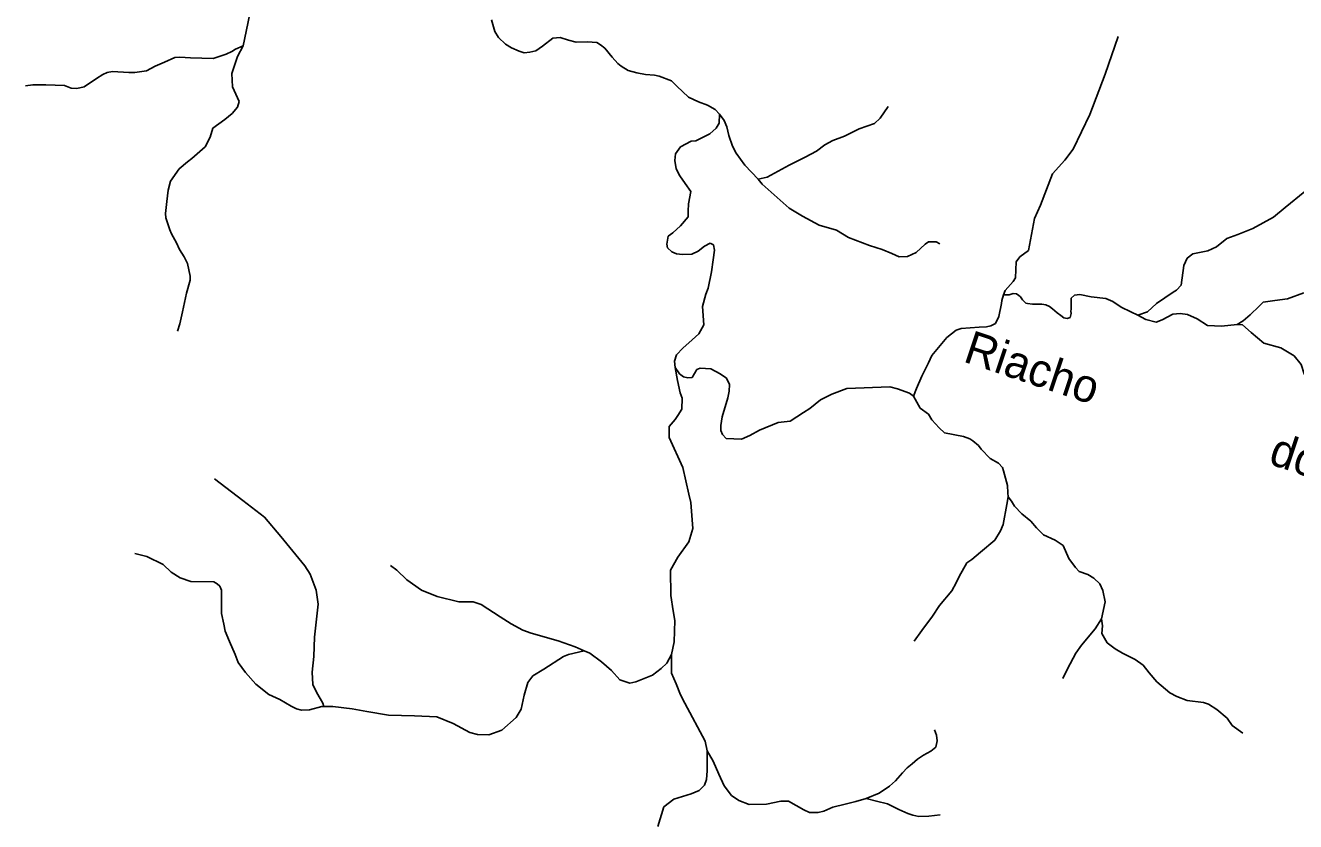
# Model space of a CAD drawing. Extents: x 717.8 to 772.7, y 8672.2 to 8728.
# Drawn here: x 725.59 to 733.27, y 8710.22 to 8715.03 of the extents above; entities that cross this region are included whole.
import ezdxf
from ezdxf.enums import TextEntityAlignment as Align

# ---------------------------------------------------------------- set-up
doc = ezdxf.new("R2010")
doc.units = 0
doc.header["$LTSCALE"] = 0.08
doc.linetypes.add('LONG_DASHED', pattern=[7.5, 6, -1.5])
doc.layers.add('61', color=7, linetype='Continuous')
doc.layers.add('9', color=7, linetype='LONG_DASHED', lineweight=25)

msp = doc.modelspace()

# ---------------------------------------------------------------- linework, layer by layer
at = {"layer": '9'}
for points in [[(726.9071, 8714.9093), (726.935, 8715.0449), (726.9507, 8715.1235), (726.9547, 8715.1579), (727.0132, 8715.2749), (727.0615, 8715.3649), (727.0853, 8715.4872), (727.1001, 8715.5623)], [(729.7892, 8714.4975), (729.762, 8714.5245), (729.7159, 8714.5507), (729.6618, 8714.5718), (729.5998, 8714.5997), (729.5303, 8714.6663), (729.4979, 8714.6976), (729.4239, 8714.7261), (729.3941, 8714.7321), (729.3402, 8714.7378), (729.2884, 8714.7464), (729.2355, 8714.7618), (729.1936, 8714.7871), (729.1729, 8714.8033), (729.1387, 8714.8415), (729.0955, 8714.8961), (729.0678, 8714.9167), (729.0459, 8714.9303), (728.9889, 8714.9335), (728.9206, 8714.9318), (728.8752, 8714.9442), (728.8241, 8714.9599), (728.7794, 8714.9568), (728.7179, 8714.9073), (728.6775, 8714.8794), (728.6416, 8714.8714), (728.6064, 8714.8686), (728.5765, 8714.8774), (728.5294, 8714.8971), (728.494, 8714.9206), (728.4507, 8714.9599), (728.4284, 8714.9966), (728.4091, 8715.0664)], [(732.2004, 8714.9657), (732.122, 8714.7385), (732.0276, 8714.4957), (731.9275, 8714.2859), (731.8778, 8714.2191), (731.8025, 8714.1357), (731.729, 8713.9473), (731.6932, 8713.8671), (731.6582, 8713.673), (731.6051, 8713.6341), (731.5824, 8713.6042), (731.5796, 8713.5085), (731.5639, 8713.485), (731.5156, 8713.4318), (731.5053, 8713.4058)], [(725.5897, 8714.6689), (725.6337, 8714.6746), (725.7132, 8714.674), (725.8271, 8714.6701), (725.8657, 8714.6538), (725.9018, 8714.653), (725.9451, 8714.6614), (726.0195, 8714.7132), (726.0587, 8714.7367), (726.0841, 8714.7499), (726.1175, 8714.7545), (726.2159, 8714.7485), (726.2512, 8714.7485), (726.3221, 8714.7598), (726.3738, 8714.7864), (726.4319, 8714.8113), (726.4937, 8714.8392), (726.5241, 8714.8408), (726.5883, 8714.8385), (726.7257, 8714.8339), (726.804, 8714.8598), (726.8378, 8714.8761), (726.8599, 8714.8897), (726.9071, 8714.9093)], [(726.5089, 8713.1846), (726.5229, 8713.2305), (726.54, 8713.3016), (726.5632, 8713.4155), (726.586, 8713.4937), (726.5871, 8713.5173), (726.5708, 8713.5933), (726.5503, 8713.6343), (726.5226, 8713.6792), (726.5032, 8713.7198), (726.4732, 8713.7741), (726.4637, 8713.7979), (726.4391, 8713.8703), (726.4376, 8713.8961), (726.4461, 8713.9688), (726.4531, 8714.0378), (726.4681, 8714.0924), (726.5199, 8714.1663), (726.5697, 8714.2081), (726.5972, 8714.2284), (726.6768, 8714.2992), (726.7072, 8714.358), (726.7243, 8714.412), (726.7964, 8714.4651), (726.8397, 8714.5001), (726.8735, 8714.5392), (726.8818, 8714.5738), (726.8434, 8714.6615), (726.8393, 8714.7431), (726.8722, 8714.8448), (726.9071, 8714.9093)], [(730.8077, 8714.5436), (730.7611, 8714.4719), (730.7252, 8714.4415), (730.6332, 8714.4083), (730.544, 8714.3646), (730.4747, 8714.3384), (730.4264, 8714.3121), (730.3757, 8714.2725), (730.3068, 8714.2377), (730.2094, 8714.1893), (730.0764, 8714.1169), (730.0219, 8714.1041)], [(729.7892, 8714.4975), (729.7858, 8714.4426), (729.7672, 8714.4119), (729.7304, 8714.3778), (729.6441, 8714.3349), (729.6163, 8714.3343), (729.5522, 8714.2992), (729.5215, 8714.2567), (729.5172, 8714.2179), (729.5258, 8714.1663), (729.549, 8714.125), (729.5798, 8714.0778), (729.6139, 8714.0305), (729.6003, 8713.9549), (729.5997, 8713.9116), (729.598, 8713.8763), (729.553, 8713.8211), (729.5058, 8713.7789), (729.4768, 8713.7596), (729.4694, 8713.7112), (729.4741, 8713.6881), (729.5001, 8713.6656), (729.528, 8713.6537), (729.5639, 8713.648), (729.6202, 8713.6514), (729.6595, 8713.669), (729.6976, 8713.6981), (729.7324, 8713.7169), (729.7523, 8713.7072), (729.7588, 8713.6752), (729.7493, 8713.6168), (729.7408, 8713.5435), (729.7203, 8713.4448), (729.7055, 8713.409), (729.6861, 8713.3349), (729.6936, 8713.2232), (729.664, 8713.1697), (729.6235, 8713.1333), (729.5666, 8713.082), (729.5273, 8713.0422), (729.5167, 8713.0048), (729.521, 8712.966)], [(730.0219, 8714.1041), (729.9424, 8714.1897), (729.8889, 8714.2609), (729.8661, 8714.3036), (729.845, 8714.368), (729.8336, 8714.4204), (729.8171, 8714.4579), (729.7892, 8714.4975)], [(731.122, 8713.7124), (731.0993, 8713.7252), (731.0534, 8713.7247), (731.0327, 8713.7118), (730.9776, 8713.6598), (730.9256, 8713.6361), (730.8744, 8713.6342), (730.8299, 8713.6551), (730.7721, 8713.6799), (730.6958, 8713.7026), (730.5694, 8713.7519), (730.4951, 8713.7959), (730.3909, 8713.8262), (730.2906, 8713.8797), (730.2106, 8713.9289), (730.1361, 8713.9928), (730.0461, 8714.0743), (730.0219, 8714.1041)], [(733.3287, 8714.0302), (733.2095, 8713.9332), (733.1391, 8713.874), (733.0146, 8713.8062), (732.9237, 8713.7693), (732.8581, 8713.7452), (732.7956, 8713.6954), (732.743, 8713.6713), (732.6514, 8713.6532), (732.618, 8713.6258), (732.5967, 8713.5832), (732.5811, 8713.464), (732.5523, 8713.4341), (732.5329, 8713.4203), (732.4815, 8713.386), (732.4317, 8713.3528), (732.3775, 8713.303), (732.3191, 8713.2816)], [(731.5053, 8713.4058), (731.4957, 8713.3712), (731.4932, 8713.3517), (731.4771, 8713.2747), (731.4568, 8713.2314), (731.4294, 8713.2172), (731.4038, 8713.2119), (731.3587, 8713.2093), (731.2492, 8713.2022), (731.2197, 8713.1921), (731.1644, 8713.1465), (731.0725, 8713.0387), (731.0524, 8712.9948), (731.0127, 8712.9134), (730.9792, 8712.8392), (730.9625, 8712.7932)], [(732.3191, 8713.2816), (732.2757, 8713.3023), (732.2186, 8713.3302), (732.1673, 8713.3639), (732.1251, 8713.3834), (732.0374, 8713.3923), (731.9682, 8713.4072), (731.9354, 8713.4027), (731.9161, 8713.3842), (731.9148, 8713.3436), (731.9148, 8713.318), (731.9142, 8713.306), (731.9161, 8713.2916), (731.9098, 8713.268), (731.8911, 8713.2625), (731.8708, 8713.2659), (731.853, 8713.2805), (731.8306, 8713.2965), (731.8032, 8713.3193), (731.785, 8713.3349), (731.7624, 8713.3453), (731.7384, 8713.3486), (731.7167, 8713.3484), (731.6816, 8713.3484), (731.6515, 8713.3519), (731.6418, 8713.3551), (731.6201, 8713.3754), (731.6086, 8713.3937), (731.599, 8713.4013), (731.5845, 8713.411), (731.5637, 8713.4126), (731.5397, 8713.4046), (731.5053, 8713.4058)], [(733.3234, 8713.4163), (733.2248, 8713.3798), (733.1479, 8713.3712), (733.0764, 8713.3603), (733.0523, 8713.3355), (732.9985, 8713.2846), (732.9551, 8713.2469), (732.9198, 8713.226)], [(732.9198, 8713.226), (732.8255, 8713.2158), (732.7404, 8713.2198), (732.6768, 8713.2607), (732.6184, 8713.2867), (732.5744, 8713.2924), (732.5307, 8713.2873), (732.4665, 8713.2529), (732.4295, 8713.2388), (732.3681, 8713.2548), (732.3191, 8713.2816)], [(733.4456, 8712.6209), (733.4562, 8712.6816), (733.4518, 8712.7731), (733.3699, 8712.8568), (733.3249, 8712.9283), (733.307, 8712.9842), (733.2635, 8713.0371), (733.1843, 8713.0845), (733.0802, 8713.1117), (733.0049, 8713.177), (732.9521, 8713.2236), (732.9198, 8713.226)], [(729.4978, 8711.2305), (729.5145, 8711.3076), (729.5186, 8711.4352), (729.5082, 8711.4948), (729.4934, 8711.587), (729.4928, 8711.7413), (729.5357, 8711.8195), (729.6033, 8711.9118), (729.6278, 8711.9916), (729.6158, 8712.1488), (729.6031, 8712.2008), (729.5661, 8712.3607), (729.483, 8712.5432), (729.4836, 8712.6092), (729.5195, 8712.6503), (729.5359, 8712.6747), (729.561, 8712.714), (729.5633, 8712.78), (729.5502, 8712.8119), (729.5343, 8712.8865), (729.521, 8712.966)], [(729.521, 8712.966), (729.5469, 8712.9273), (729.57, 8712.9097), (729.5973, 8712.9034), (729.6224, 8712.9057), (729.6514, 8712.9535), (729.672, 8712.9617), (729.7367, 8712.9574), (729.7928, 8712.9273), (729.8316, 8712.9014), (729.8488, 8712.8627), (729.8473, 8712.8218), (729.8387, 8712.7831), (729.8042, 8712.6667), (729.8001, 8712.6413), (729.7957, 8712.6149), (729.7957, 8712.5847), (729.8055, 8712.5599), (729.8282, 8712.536), (729.921, 8712.5324), (729.9726, 8712.5546), (730.0305, 8712.5863), (730.1428, 8712.6341), (730.2152, 8712.6413), (730.296, 8712.6926), (730.3349, 8712.7185), (730.3984, 8712.7694), (730.4685, 8712.8047), (730.5592, 8712.8392), (730.8181, 8712.8479), (730.8644, 8712.8375), (730.9385, 8712.8109), (730.9625, 8712.7932)], [(730.9625, 8712.7932), (731.003, 8712.7207), (731.0533, 8712.6827), (731.0724, 8712.6491), (731.1173, 8712.6012), (731.1502, 8712.5707), (731.2651, 8712.5479), (731.3034, 8712.5336), (731.3214, 8712.5222), (731.3543, 8712.4941), (731.3709, 8712.4729), (731.4262, 8712.4145), (731.4753, 8712.3864), (731.5005, 8712.3608), (731.507, 8712.3409), (731.5308, 8712.253), (731.5329, 8712.2086), (731.5339, 8712.1829)], [(726.7339, 8712.2919), (726.9051, 8712.1611), (727.0353, 8712.061), (727.1348, 8711.9447), (727.1889, 8711.8771), (727.2791, 8711.7672), (727.3117, 8711.7159), (727.349, 8711.6204), (727.3602, 8711.5345), (727.3378, 8711.3362), (727.3334, 8711.219), (727.3243, 8711.1243), (727.3286, 8711.0501), (727.35, 8711.0021), (727.388, 8710.9359), (727.3947, 8710.9165)], [(730.9659, 8711.3104), (731.0128, 8711.3756), (731.0764, 8711.4624), (731.1181, 8711.526), (731.1946, 8711.6157), (731.2205, 8711.6632), (731.2378, 8711.7019), (731.2851, 8711.7839), (731.3154, 8711.8055), (731.3672, 8711.8486), (731.4534, 8711.9219), (731.4879, 8711.978), (731.5051, 8712.0168), (731.5266, 8712.1375), (731.5339, 8712.1829)], [(732.0998, 8711.4464), (732.1221, 8711.5481), (732.1069, 8711.6184), (732.0879, 8711.6582), (732.0525, 8711.6924), (732.0173, 8711.714), (731.9639, 8711.7316), (731.9425, 8711.756), (731.9015, 8711.8104), (731.8662, 8711.8894), (731.8186, 8711.9224), (731.7475, 8711.9541), (731.7061, 8711.9964), (731.6713, 8712.0374), (731.6162, 8712.0817), (731.5737, 8712.1278), (731.5551, 8712.1575), (731.5339, 8712.1829)], [(726.2514, 8711.8414), (726.3234, 8711.8233), (726.4225, 8711.7737), (726.472, 8711.7286), (726.5255, 8711.6931), (726.5897, 8711.6717), (726.7293, 8711.6709), (726.7503, 8711.658), (726.7664, 8711.643), (726.7757, 8711.6192), (726.7765, 8711.4793), (726.7903, 8711.4147), (726.7975, 8711.3707), (726.8235, 8711.3091), (726.8579, 8711.2314), (726.8772, 8711.1813), (726.9216, 8711.1228), (726.9828, 8711.0514), (727.0623, 8710.9892), (727.1289, 8710.9577), (727.1971, 8710.9174), (727.2293, 8710.902), (727.2605, 8710.8941), (727.3089, 8710.8959), (727.3821, 8710.9165), (727.3947, 8710.9165)], [(727.799, 8711.768), (727.8372, 8711.7412), (727.8975, 8711.6826), (727.986, 8711.6192), (728.0806, 8711.5805), (728.2111, 8711.5482), (728.2982, 8711.5498), (728.3471, 8711.5321), (728.4616, 8711.4574), (728.5288, 8711.4166), (728.5981, 8711.3779), (728.6492, 8711.3591), (728.8124, 8711.3128), (728.916, 8711.2766), (728.9698, 8711.252)], [(731.8641, 8711.0864), (731.8928, 8711.1446), (731.9429, 8711.2393), (731.9784, 8711.287), (732.061, 8711.3861), (732.0998, 8711.4464)], [(732.9533, 8710.7545), (732.8903, 8710.8022), (732.8586, 8710.8456), (732.7971, 8710.8978), (732.7469, 8710.9299), (732.7151, 8710.9403), (732.6167, 8710.9531), (732.5556, 8710.977), (732.5116, 8710.999), (732.434, 8711.0663), (732.3882, 8711.1188), (732.3503, 8711.1659), (732.3023, 8711.2002), (732.2255, 8711.2393), (732.1825, 8711.265), (732.1336, 8711.3004), (732.1012, 8711.3585), (732.1042, 8711.4034), (732.0998, 8711.4464)], [(727.3947, 8710.9165), (727.4498, 8710.9165), (727.5668, 8710.9028), (727.655, 8710.8867), (727.7857, 8710.8641), (727.9442, 8710.8591), (728.0782, 8710.8535), (728.1779, 8710.8138), (728.2771, 8710.7597), (728.3251, 8710.7466), (728.3931, 8710.745), (728.4715, 8710.7731), (728.5589, 8710.8504), (728.5885, 8710.9), (728.6058, 8710.985), (728.6282, 8711.0617), (728.6597, 8711.1011), (728.7256, 8711.1419), (728.8442, 8711.2178), (728.8753, 8711.2313), (728.9698, 8711.252)], [(728.9698, 8711.252), (729.0032, 8711.2393), (729.0747, 8711.1867), (729.1356, 8711.134), (729.1857, 8711.078), (729.2457, 8711.058), (729.2822, 8711.0657), (729.3827, 8711.1061), (729.436, 8711.1462), (729.4702, 8711.1781), (729.4978, 8711.2305)], [(729.4978, 8711.2305), (729.4975, 8711.1175), (729.5254, 8711.0533), (729.5527, 8710.9868), (729.5787, 8710.9357), (729.701, 8710.7077), (729.7128, 8710.6487)], [(731.0881, 8710.7751), (731.1018, 8710.7437), (731.1057, 8710.7084), (731.0969, 8710.6712), (731.0675, 8710.6461), (731.0224, 8710.6221), (730.9856, 8710.5981), (730.9542, 8710.5701), (730.9229, 8710.5447), (730.8949, 8710.5147), (730.8537, 8710.4671), (730.8173, 8710.4344), (730.7536, 8710.392), (730.6745, 8710.3593)], [(729.4156, 8710.1901), (729.4158, 8710.1904), (729.4523, 8710.3106), (729.5125, 8710.3558), (729.6175, 8710.3882), (729.6659, 8710.4084), (729.6985, 8710.4413), (729.7099, 8710.4755), (729.714, 8710.5267), (729.714, 8710.5765), (729.7128, 8710.6487)], [(730.6745, 8710.3593), (730.6122, 8710.3415), (730.549, 8710.3255), (730.4745, 8710.3069), (730.4201, 8710.2843), (730.3847, 8710.2763), (730.3336, 8710.2752), (730.2982, 8710.2917), (730.2048, 8710.3436), (730.1593, 8710.3441), (730.0723, 8710.3255), (729.9685, 8710.3244), (729.9046, 8710.3488), (729.8614, 8710.378), (729.8161, 8710.4357), (729.7849, 8710.5082), (729.7494, 8710.5864), (729.7128, 8710.6487)], [(731.1236, 8710.2619), (731.0549, 8710.2537), (730.9948, 8710.2511), (730.9576, 8710.2594), (730.9276, 8710.2697), (730.8727, 8710.2941), (730.8041, 8710.3288), (730.738, 8710.3438), (730.6745, 8710.3593)]]:
    msp.add_lwpolyline(points, dxfattribs=at)

# ---------------------------------------------------------------- texts
at = {"layer": '61'}
msp.add_text('Riacho               do  Arroz', height=0.2, rotation=341.509, dxfattribs=at).set_placement((732.6932, 8712.5226), align=Align.CENTER)

doc.saveas('drawing.dxf')
